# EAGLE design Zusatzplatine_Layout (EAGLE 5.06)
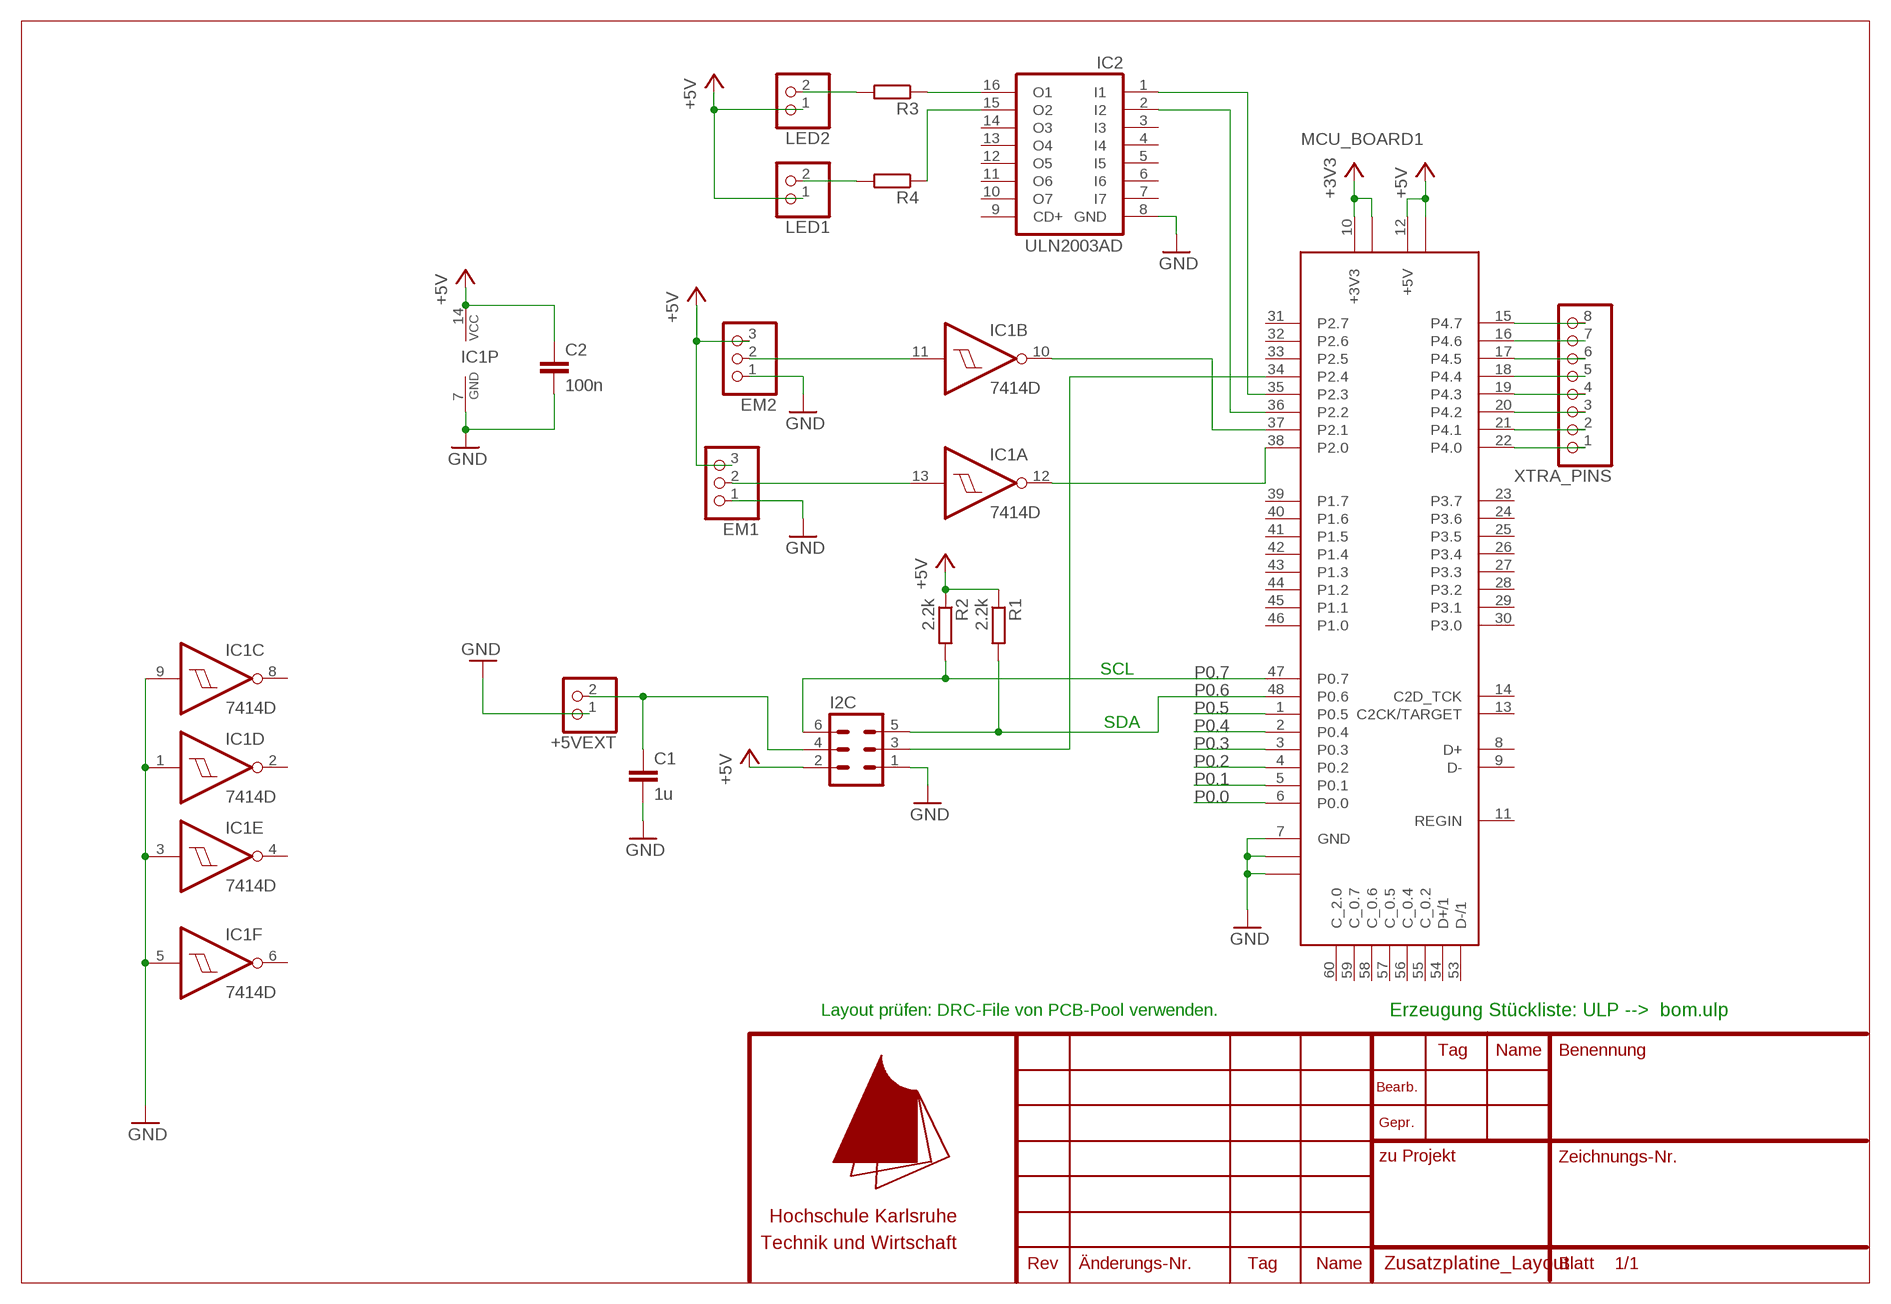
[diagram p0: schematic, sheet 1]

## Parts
+5VEXT  PINHD-1X2  [1X02]
C1  1u  C-EU025-025X050  [C025-025X050]
C2  100n  C-EUC1206  [C1206]
EM1  PINHD-1X3  [1X03]
EM2  PINHD-1X3  [1X03]
I2C  ML6  [ML6]
IC1  7414D  [SO14]
IC2  ULN2003AD  [SO16]
LED1  PINHD-1X2  [1X02]
LED2  PINHD-1X2  [1X02]
MCU_BOARD1  MCU_BOARDGEGENSTÜCK  [MCU_BOARD]
R1  2.2k  R-EU_R1206  [R1206]
R2  2.2k  R-EU_R1206  [R1206]
R3  R-EU_R1206  [R1206]
R4  R-EU_R1206  [R1206]
XTRA_PINS  PINHD-1X8  [1X08]

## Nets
+3V3: MCU_BOARD1.10(+3V3) MCU_BOARD1.49(+3V31)
+5V: C2.1 EM1.3 EM2.3 I2C.2 IC1.14(P:VCC) LED1.1 LED2.1 MCU_BOARD1.12(+5V) MCU_BOARD1.50(+5V1) R1.1 R2.1
GND: +5VEXT.1 C1.2 C2.2 EM1.1 EM2.1 I2C.1 IC1.1(D:I) IC1.3(E:I) IC1.5(F:I) IC1.7(P:GND) IC1.9(C:I) IC2.8(GND) MCU_BOARD1.7(GND) MCU_BOARD1.51(GND1) MCU_BOARD1.52(GND2)
N$1: IC1.12(A:O) MCU_BOARD1.38(P2.0)
N$2: IC1.10(B:O) MCU_BOARD1.37(P2.1)
N$3: EM1.2 IC1.13(A:I)
N$4: EM2.2 IC1.11(B:I)
N$5: IC2.2(I2) MCU_BOARD1.36(P2.2)
N$6: IC2.1(I1) MCU_BOARD1.35(P2.3)
N$7: +5VEXT.2 C1.1 I2C.4
N$8: I2C.3 MCU_BOARD1.34(P2.4)
N$9: MCU_BOARD1.22(P4.0) XTRA_PINS.1
N$10: MCU_BOARD1.21(P4.1) XTRA_PINS.2
N$11: MCU_BOARD1.20(P4.2) XTRA_PINS.3
N$12: MCU_BOARD1.19(P4.3) XTRA_PINS.4
N$13: MCU_BOARD1.18(P4.4) XTRA_PINS.5
N$14: MCU_BOARD1.17(P4.5) XTRA_PINS.6
N$15: MCU_BOARD1.16(P4.6) XTRA_PINS.7
N$16: MCU_BOARD1.15(P4.7) XTRA_PINS.8
N$17: LED1.2 R4.2
N$18: LED2.2 R3.2
N$20: IC2.16(O1) R3.1
N$21: IC2.15(O2) R4.1
P0.0: MCU_BOARD1.6(P0.0)
P0.1: MCU_BOARD1.5(P0.1)
P0.2: MCU_BOARD1.4(P0.2)
P0.3: MCU_BOARD1.3(P0.3)
P0.4: MCU_BOARD1.2(P0.4)
P0.5: MCU_BOARD1.1(P0.5)
P0.6: I2C.5 MCU_BOARD1.48(P0.6) R1.2
P0.7: I2C.6 MCU_BOARD1.47(P0.7) R2.2
Unconnected: IC1.2(D:O) IC1.4(E:O) IC1.6(F:O) IC1.8(C:O) IC2.3(I3) IC2.4(I4) IC2.5(I5) IC2.6(I6) IC2.7(I7) IC2.9(CD+) IC2.10(O7) IC2.11(O6) IC2.12(O5) IC2.13(O4) IC2.14(O3) MCU_BOARD1.8(D+) MCU_BOARD1.9(D-) MCU_BOARD1.11(REGIN) MCU_BOARD1.13(C2CK/TARGET) MCU_BOARD1.14(C2D_TCK) MCU_BOARD1.23(P3.7) MCU_BOARD1.24(P3.6) MCU_BOARD1.25(P3.5) MCU_BOARD1.26(P3.4) MCU_BOARD1.27(P3.3) MCU_BOARD1.28(P3.2) MCU_BOARD1.29(P3.1) MCU_BOARD1.30(P3.0) MCU_BOARD1.31(P2.7) MCU_BOARD1.32(P2.6) MCU_BOARD1.33(P2.5) MCU_BOARD1.39(P1.7) MCU_BOARD1.40(P1.6) MCU_BOARD1.41(P1.5) MCU_BOARD1.42(P1.4) MCU_BOARD1.43(P1.3) MCU_BOARD1.44(P1.2) MCU_BOARD1.45(P1.1) MCU_BOARD1.46(P1.0) MCU_BOARD1.53(D-/1) MCU_BOARD1.54(D+/1) MCU_BOARD1.55(C_0.2) MCU_BOARD1.56(C_0.4) MCU_BOARD1.57(C_0.5) MCU_BOARD1.58(C_0.6) MCU_BOARD1.59(C_0.7) MCU_BOARD1.60(C_2.0)

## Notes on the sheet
- SCL
- SDA
- Layout prüfen: DRC-File von PCB-Pool verwenden. | Erzeugung Stückliste: ULP -->  bom.ulp

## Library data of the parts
+5VEXT LED1 LED2 = pinhead:PINHD-1X2: PIN HEADER
C1 C2 = rcl:C-EU: CAPACITOR, European symbol
EM1 EM2 = pinhead:PINHD-1X3: PIN HEADER
I2C = con-ml:ML6: HARTING
IC1 = 74xx-eu:74*14: Hex schmitt trigger INVERTER
IC2 = uln-udn:ULN2003A: DRIVER ARRAY
MCU_BOARD1 = M_MCU-Board:MCU_BOARD: Silabs MCU Aufsteckboard. Symbol & Package by Nicolas Reibel nik2004@gmx.de 12/2007
R1-R4 = rcl:R-EU_: RESISTOR, European symbol
XTRA_PINS = pinhead:PINHD-1X8: PIN HEADER

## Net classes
0 default: width 0.152 mm, drill 0.305 mm, clearance 0.4 mm
1 5V: width 0.305 mm, drill 0.305 mm, clearance 0.4 mm
2 3V3: width 0.305 mm, drill 0.305 mm, clearance 0.4 mm

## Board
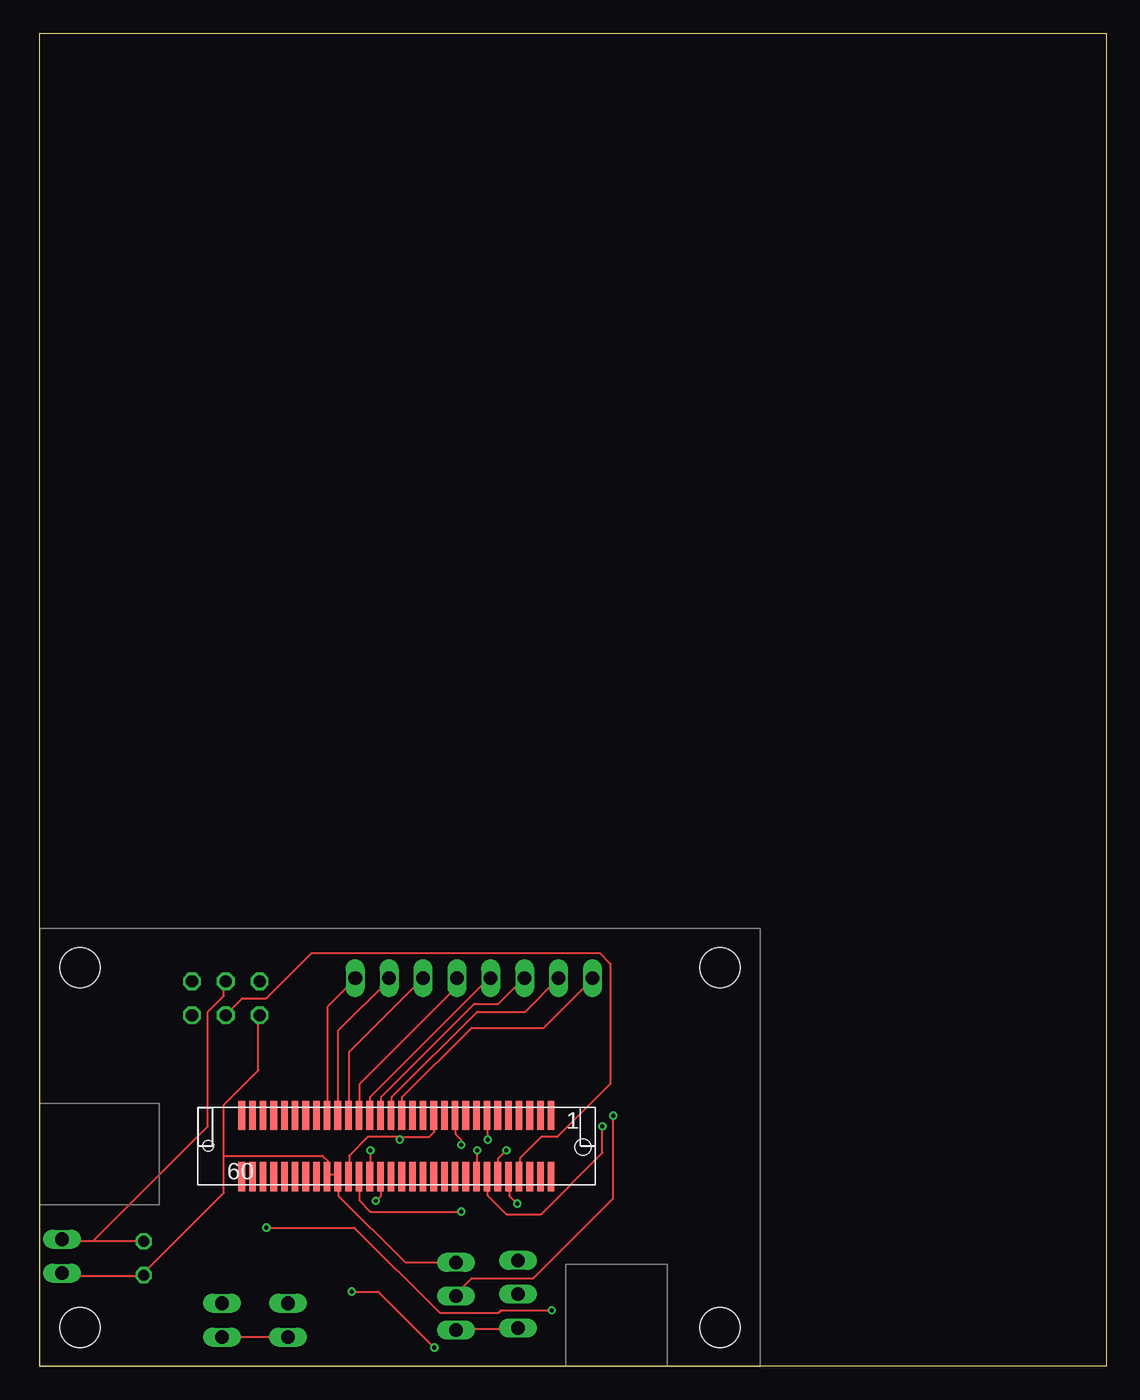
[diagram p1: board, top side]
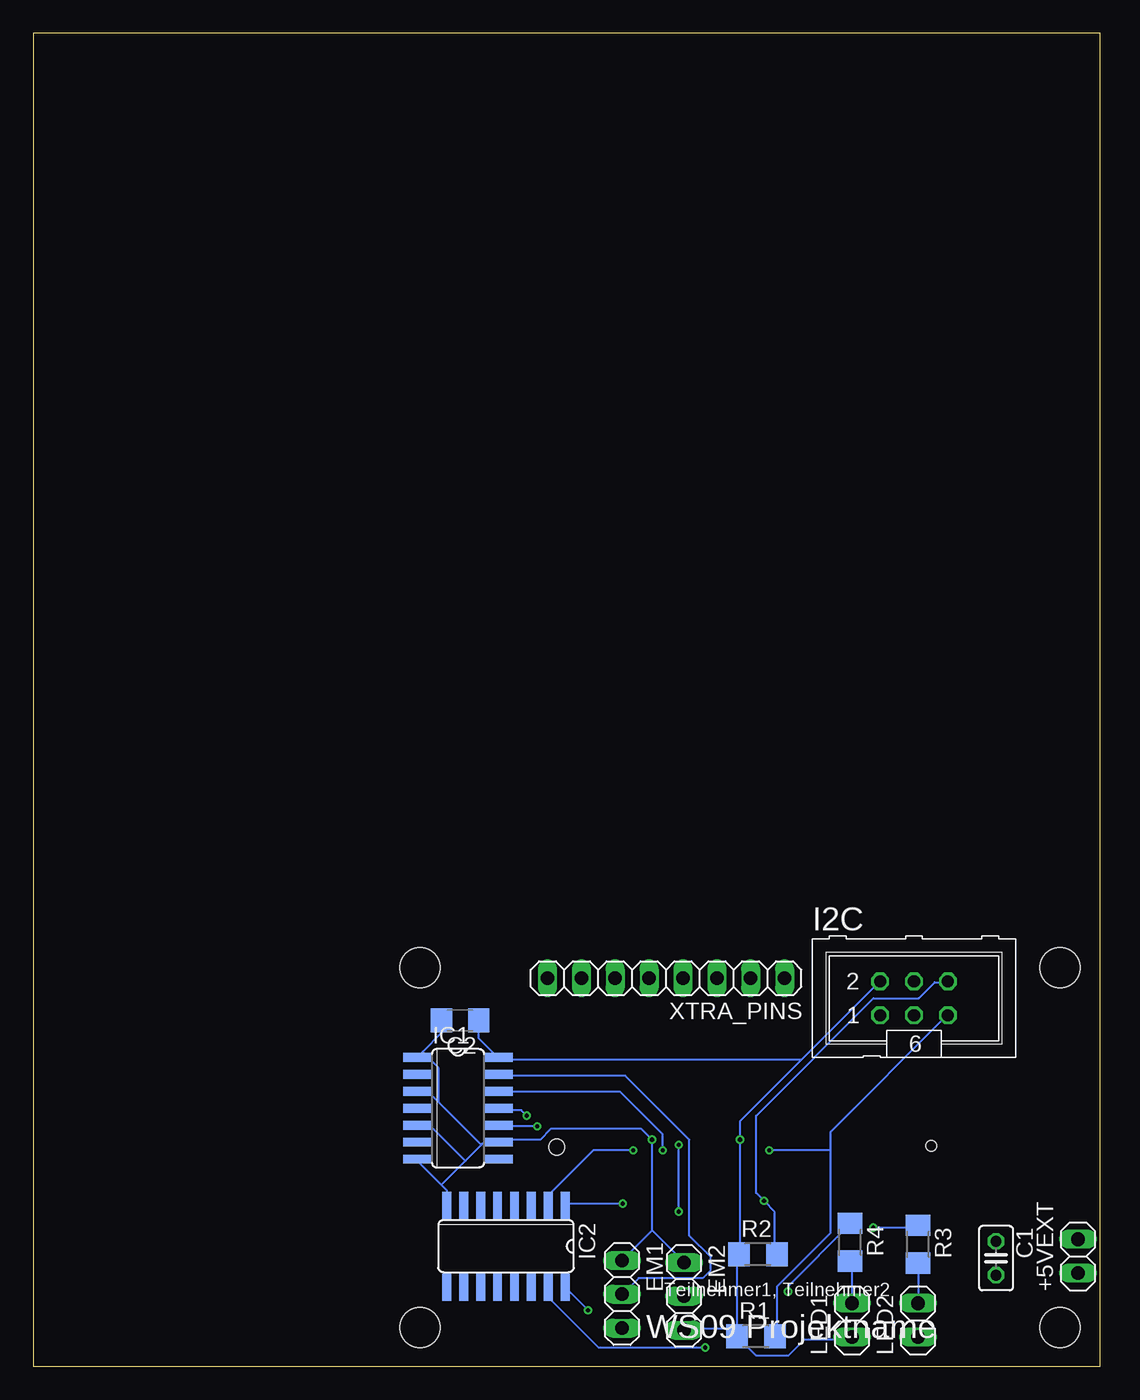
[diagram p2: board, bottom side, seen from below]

Size 80 x 100 mm. Coordinates in mm from the lower left corner, seen from the top.
Outline: 0,0 0,100 80,100 80,0 0,0
Copper layers (1*16): Top 0.035mm / dielectric 1.5mm / Bottom 0.035mm
Design rules "PCB-POOL": minimum track width 6mil, minimum drill 12mil, track to track 6mil, track to pad 6mil, pad to pad 6mil, via to via 6mil, smd to smd 6mil, copper to edge 20mil, drill to drill 8mil, minimum pad ring 8mil, minimum via ring 6mil, stop-mask expansion 3mil, vias tented up to drill 0mil, thermal gap 8mil

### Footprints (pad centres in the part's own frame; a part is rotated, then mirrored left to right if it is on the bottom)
1X02 = drill 1.016 long: 1 -1.27,0; 2 1.27,0
C025-025X050 = drill 0.813 octagon: 1 -1.27,0; 2 1.27,0
C1206 = smd 1.6 x 1.8: 1 -1.4,0; 2 1.4,0
1X03 = drill 1.016 long: 1 -2.54,0; 2 0,0; 3 2.54,0
ML6 = drill 0.914 octagon: 1 -2.54,-1.27; 2 -2.54,1.27; 3 0,-1.27; 4 0,1.27; 5 2.54,-1.27; 6 2.54,1.27
SO14 = smd 0.66 x 2.032: 1 -3.81,-3.073; 2 -2.54,-3.073; 3 -1.27,-3.073; 4 0,-3.073; 5 1.27,-3.073; 6 2.54,-3.073; 7 3.81,-3.073; 8 3.81,3.073; 9 2.54,3.073; 10 1.27,3.073; 11 0,3.073; 12 -1.27,3.073; 13 -2.54,3.073; 14 -3.81,3.073
SO16 = smd 0.66 x 2.032: 1 -4.445,-3.073; 2 -3.175,-3.073; 3 -1.905,-3.073; 4 -0.635,-3.073; 5 0.635,-3.073; 6 1.905,-3.073; 7 3.175,-3.073; 8 4.445,-3.073; 9 4.445,3.073; 10 3.175,3.073; 11 1.905,3.073; 12 0.635,3.073; 13 -0.635,3.073; 14 -1.905,3.073; 15 -3.175,3.073; 16 -4.445,3.073
MCU_BOARD = smd 0.5 x 2.2: 1 11.612,2.274; 2 10.812,2.274; 3 10.012,2.274; 4 9.212,2.274; 5 8.412,2.274; 6 7.612,2.274; 7 6.812,2.274; 8 6.012,2.274; 9 5.212,2.274; 10 4.412,2.274; 11 3.612,2.274; 12 2.812,2.274; 13 2.012,2.274; 14 1.212,2.274; 15 0.412,2.274; 16 -0.388,2.274; 17 -1.188,2.274; 18 -1.988,2.274; 19 -2.788,2.274; 20 -3.588,2.274; 21 -4.388,2.274; 22 -5.188,2.274; 23 -5.988,2.274; 24 -6.788,2.274; 25 -7.588,2.274; 26 -8.388,2.274; 27 -9.188,2.274; 28 -9.988,2.274; 29 -10.788,2.274; 30 -11.588,2.274; 31 11.612,-2.326; 32 10.812,-2.326; 33 10.012,-2.326; 34 9.212,-2.326; 35 8.412,-2.326; 36 7.612,-2.326; 37 6.812,-2.326; 38 6.012,-2.326; 39 5.212,-2.326; 40 4.412,-2.326; 41 3.612,-2.326; 42 2.812,-2.326; 43 2.012,-2.326; 44 1.212,-2.326; 45 0.412,-2.326; 46 -0.388,-2.326; 47 -1.188,-2.326; 48 -1.988,-2.326; 49 -2.788,-2.326; 50 -3.588,-2.326; 51 -4.388,-2.326; 52 -5.188,-2.326; 53 -5.988,-2.326; 54 -6.788,-2.326; 55 -7.588,-2.326; 56 -8.388,-2.326; 57 -9.188,-2.326; 58 -9.988,-2.326; 59 -10.788,-2.326; 60 -11.588,-2.326 | hole 3: -23.728,-13.642; -23.728,13.358; 24.272,-13.642; 24.272,13.358 | hole 0.8: -14.1,0 | hole 1.2: 14,-0.1
R1206 = smd 1.6 x 1.803: 1 -1.422,0; 2 1.422,0
1X08 = drill 1.016 long: 1 -8.89,0; 2 -6.35,0; 3 -3.81,0; 4 -1.27,0; 5 1.27,0; 6 3.81,0; 7 6.35,0; 8 8.89,0

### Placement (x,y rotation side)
+5VEXT  1.65,8.25 90 bottom
C1  7.8,8.1 270 bottom
C2  48,25.95 180 bottom
EM1  35.85,5.4 270 bottom
EM2  31.2,5.25 270 bottom
I2C  13.95,27.6 0 bottom
IC1  48.15,19.35 270 bottom
IC2  44.55,9 180 bottom
LED1  18.6,3.45 90 bottom
LED2  13.65,3.45 90 bottom
MCU_BOARD1  26.74,16.54 0 top
R1  25.8,2.25 0 bottom
R2  25.65,8.4 0 bottom
R3  13.65,9.15 270 bottom
R4  18.75,9.3 270 bottom
XTRA_PINS  32.55,29.1 180 bottom

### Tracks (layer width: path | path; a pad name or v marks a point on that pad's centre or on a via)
+3V3  (via drill 0.3)
  Top 0.152: v31.6,11.6 24.8,11.6 24,12.4 24,14.2 MCU_BOARD1.49 | v31.6,16.6 31.6,17 31.2,17.4 31.2,18.8 MCU_BOARD1.10
  Bottom 0.152: v31.6,11.6 v31.6,16.6
+5V  (via drill 0.3)
  Top 0.152: 27,17.2 29.2,17.2 29.6,17.6 29.6,18.8 MCU_BOARD1.12 | 27,17.2 24.6,17.2 23.2,15.8 23.2,14.4 MCU_BOARD1.50 | LED2.1 13.8,2.2 18.6,2.2 LED1.1 | EM1.3 35.8,2.8 31.2,2.8 EM2.3 | v27,17 27,17.2
  Bottom 0.152: C2.1 46.6,24.6 45.2,23.2 IC1.14 45,23 22.4,23 | 27.2,2.8 27.2,2.4 R1.1 | 27.2,2.8 27.2,8.4 R2.1 27,8.4 v27,17 27,18.4 22.4,23 | 22.4,23 16.6,28.8 I2C.2 | 27.2,2.8 31.2,2.8 EM2.3 | R1.1 27.2,2.8 | LED1.1 18.6,2 22.2,2 23.4,0.8 25.8,0.8 27.2,2.2 R1.1
GND  (via drill 0.3)
  Top 0.152: +5VEXT.1 1.8,6.8 7.8,6.8 C1.2 7.8,7 13.8,13 13.8,15.8 | 13.8,15.8 13.8,19.6 16.4,22.2 16.4,26.2 I2C.1 | v33.6,17 33.6,18.8 MCU_BOARD1.7 | 21.6,14.4 22.2,14.4 MCU_BOARD1.51 22.4,14.2 22.4,12.8 27.4,7.8 EM2.1 | 13.8,15.8 21.2,15.8 21.6,15.4 21.6,14.4 | 21.6,14.4 MCU_BOARD1.52
  Bottom 0.152: 50.8,23.6 51.2,23.2 IC1.1 | 50.8,23.6 49.4,25 C2.2 | 49.4,13.6 51.2,15.4 IC1.7 | 49.4,13.6 49,13.2 49,12.2 IC2.8 | 47.6,15.4 49.4,13.6 | 46.4,16.6 47.6,15.4 | 46.4,16.6 46.2,16.8 45.2,16.8 IC1.9 45,17 42,17 41.2,17.8 34.4,17.8 v33.6,17 33.6,10.2 | 47.6,15.4 50.2,18 51.2,18 IC1.5 | 46.4,16.6 49.6,19.8 | 49.6,19.8 50.4,20.6 51.2,20.6 IC1.3 | 50.8,23.6 49.6,22.4 49.6,19.8 | 33.6,10.2 35.8,8 EM1.1 | 33.6,10.2 EM2.1
N$1  (via drill 0.3)
  Top 0.152: v32.8,16.2 32.8,14.4 MCU_BOARD1.38
  Bottom 0.152: v32.8,16.2 32.8,17.4 36,20.6 45,20.6 IC1.12
N$2  (via drill 0.3)
  Top 0.152: v42.2,18 42.2,16 37.6,11.4 35,11.4 33.6,12.8 33.6,14.2 MCU_BOARD1.37
  Bottom 0.152: v42.2,18 45,18 IC1.10
N$3
  Bottom 0.152: IC1.13 45,21.8 35.6,21.8 30.8,17 30.8,9.8 29.2,8.2 29.2,7.2 29.8,6.6 34.6,6.6 35.8,5.4 EM1.2
N$4  (via drill 0.3)
  Top 0.152: v43,18.8 43,12.6 37,6.6 32.4,6.6 31.2,5.4 EM2.2
  Bottom 0.152: v43,18.8 43.4,19.2 45,19.2 IC1.11
N$5  (via drill 0.3)
  Top 0.152: v35,16.2 34.4,15.6 34.4,14.4 MCU_BOARD1.36
  Bottom 0.152: v35,16.2 38,16.2 41.2,13 41.2,12.2 IC2.2
N$6  (via drill 0.3)
  Top 0.152: v35.8,12.2 35.2,12.8 35.2,14.2 MCU_BOARD1.35
  Bottom 0.152: v35.8,12.2 40,12.2 IC2.1
N$7
  Top 0.152: 4,9.4 1.8,9.4 +5VEXT.2 | 4,9.4 7.8,9.4 C1.1 | 4,9.4 12.6,18 12.6,26.6 13.8,27.8 13.8,28.8 I2C.4
N$8
  Top 0.152: MCU_BOARD1.34 36,14.4 36,15.6 37.6,17.2 38.8,17.2 42.8,21.2 42.8,30.2 42,31 20.4,31 17,27.6 15.2,27.6 14,26.4 I2C.3
N$9
  Top 0.152: MCU_BOARD1.22 21.6,19 21.6,27 23.6,29 XTRA_PINS.1
N$10
  Top 0.152: MCU_BOARD1.21 22.4,19 22.4,25.2 26.2,29 XTRA_PINS.2
N$11
  Top 0.152: MCU_BOARD1.20 23.2,19 23.2,23.6 28.6,29 XTRA_PINS.3
N$12
  Top 0.152: MCU_BOARD1.19 24,19 24,21.2 31.2,28.4 31.2,29 XTRA_PINS.4
N$13
  Top 0.152: MCU_BOARD1.18 24.8,19 24.8,20.2 33.8,29.2 XTRA_PINS.5
N$14
  Top 0.152: MCU_BOARD1.17 25.6,19 25.6,20.2 32.6,27.2 34.4,27.2 36.2,29 XTRA_PINS.6
N$15
  Top 0.152: MCU_BOARD1.16 26.4,19 26.4,20.2 32.8,26.6 36.4,26.6 XTRA_PINS.7
N$16
  Top 0.152: MCU_BOARD1.15 27.2,19 27.2,20.2 32.4,25.4 37.8,25.4 41.4,29 XTRA_PINS.8
N$17
  Bottom 0.152: R4.2 18.6,7.8 LED1.2
N$18
  Bottom 0.152: R3.2 13.6,7.6 13.6,4.8 LED2.2
N$20  (via drill 0.3)
  Top 0.152: v17,10.4 23.6,10.4 30,4 34.4,4 34.6,4.2 v38.4,4.2
  Bottom 0.152: v17,10.4 13.8,10.4 R3.1 | v38.4,4.2 40,5.8 IC2.16
N$21  (via drill 0.3)
  Top 0.152: v23.4,5.6 25.4,5.6 v29.6,1.4
  Bottom 0.152: v23.4,5.6 23.4,6 18.8,10.6 R4.1 | v29.6,1.4 37.6,1.4 41.2,5 41.2,5.8 IC2.15
P0.6  (via drill 0.3)
  Top 0.152: v24.8,16.2 24.8,14.4 MCU_BOARD1.48
  Bottom 0.152: 20.2,16.2 20.2,17.6 11.6,26.2 I2C.5 | 20.2,16.2 20.2,10 24.2,6 24.2,2.4 R1.2 | 20.2,16.2 v24.8,16.2
P0.7  (via drill 0.3)
  Top 0.152: v25.2,12.4 25.6,12.8 25.6,14.2 MCU_BOARD1.47
  Bottom 0.152: R2.2 24.4,8.4 24.4,11.6 v25.2,12.4 25.8,13 25.8,18.8 17,27.6 13.6,27.6 12.4,28.8 11.6,28.8 I2C.6

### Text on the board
bNames: Teilnehmer1, Teilnehmer2 | WS09 Projektname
